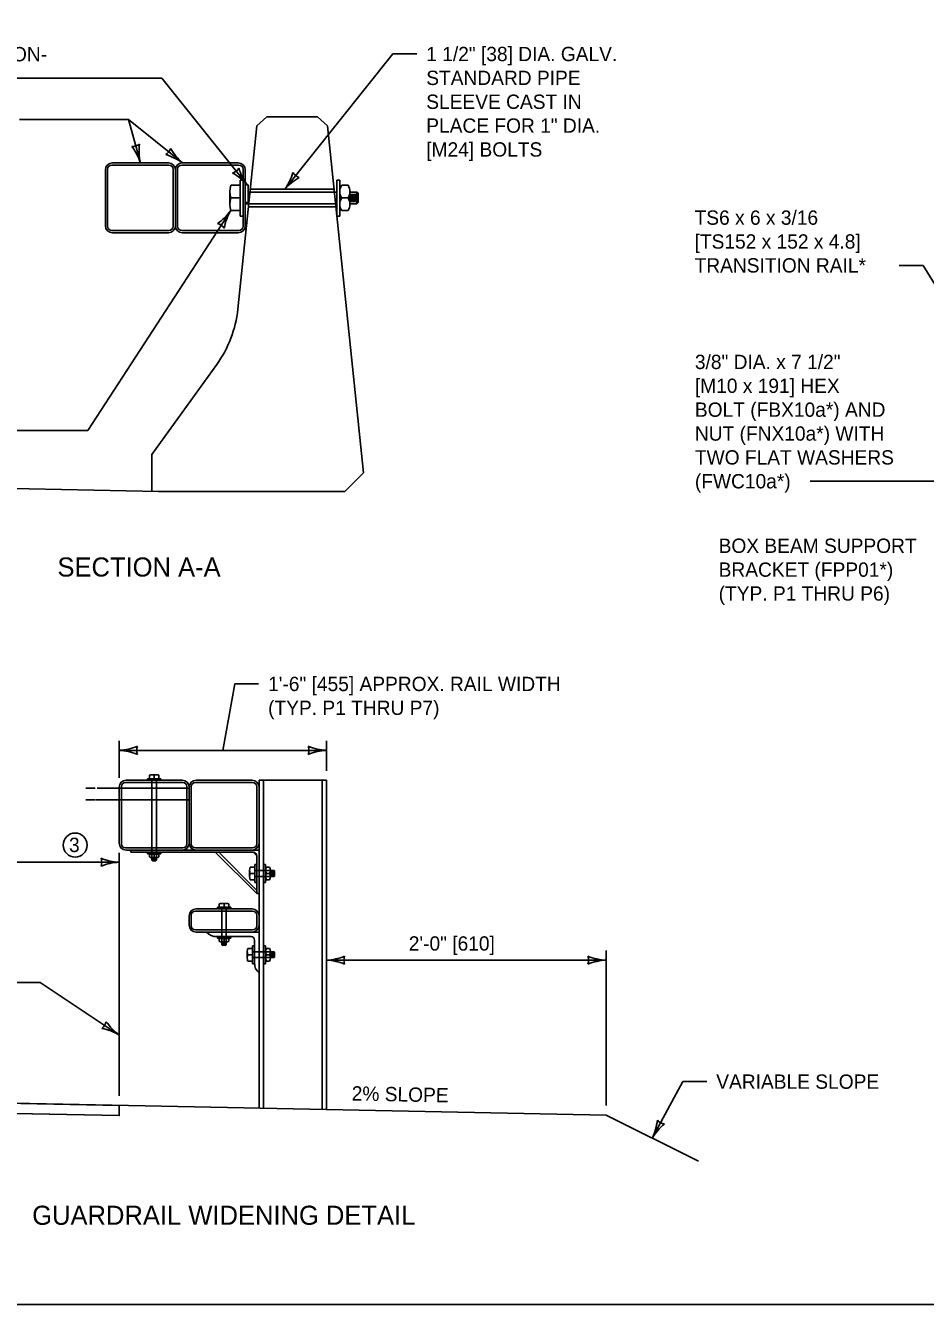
# Model space of a CAD drawing. Extents: x 49983 to 50021, y 49963.5 to 50011.4.
# Drawn here: x 50001.51 to 50005.28, y 49987.8 to 49993.16 of the extents above; entities that cross this region are included whole.
import ezdxf

# ---------------------------------------------------------------- set-up
doc = ezdxf.new("R2010")
doc.units = 0
for name, color, linetype in [('Level 1', 7, 'Continuous'), ('Level 10', 7, 'Continuous'), ('Level 2', 7, 'Continuous'), ('Level 3', 7, 'Continuous'), ('Level 4', 7, 'Continuous')]:
    doc.layers.add(name, color=color, linetype=linetype)

msp = doc.modelspace()

# ---------------------------------------------------------------- linework, layer by layer
at = {"layer": 'Level 1'}
for p, q in [((50002.5172, 49992.7754), (50002.4748, 49992.7371)), ((50002.7291, 49992.7754), (50002.5172, 49992.7754)), ((50002.7208, 49992.7754), (50002.5255, 49992.7754)), ((50002.7714, 49992.7371), (50002.7291, 49992.7754)), ((50002.4748, 49992.7371), (50002.3955, 49991.9692)), ((50002.9217, 49991.2832), (50002.7714, 49992.7371)), ((50001.8413, 49992.5533), (50001.8413, 49992.3191)), ((50001.8504, 49992.5559), (50001.8504, 49992.3165)), ((50001.868, 49992.5735), (50002.1074, 49992.5735)), ((50001.8706, 49992.5826), (50002.1048, 49992.5826)), ((50002.125, 49992.5559), (50002.125, 49992.3165)), ((50002.1341, 49992.5533), (50002.1341, 49992.3191)), ((50002.1341, 49992.5533), (50002.1341, 49992.3191)), ((50002.1433, 49992.5559), (50002.1433, 49992.3165)), ((50002.1609, 49992.5735), (50002.4002, 49992.5735)), ((50002.1634, 49992.5826), (50002.3976, 49992.5826)), ((50002.4178, 49992.5559), (50002.4178, 49992.3165)), ((50002.4269, 49992.5533), (50002.4269, 49992.3191)), ((50002.366, 49992.4885), (50002.4057, 49992.4885)), ((50002.4057, 49992.3598), (50002.4057, 49992.5101)), ((50002.4057, 49992.5101), (50002.4178, 49992.5101)), ((50002.4389, 49992.4905), (50002.4269, 49992.4905)), ((50002.4389, 49992.417), (50002.4389, 49992.4905)), ((50002.8225, 49992.5101), (50002.8104, 49992.5101)), ((50002.8104, 49992.3598), (50002.8104, 49992.5101)), ((50002.8225, 49992.3598), (50002.8225, 49992.5101)), ((50002.8573, 49992.4885), (50002.8307, 49992.4885)), ((50002.3628, 49992.409), (50002.3628, 49992.462)), ((50002.366, 49992.4355), (50002.4057, 49992.4355)), ((50002.4389, 49992.46), (50002.4462, 49992.46)), ((50002.8104, 49992.46), (50002.8001, 49992.46)), ((50002.8307, 49992.4355), (50002.8573, 49992.4355)), ((50002.8655, 49992.409), (50002.8655, 49992.462)), ((50002.8946, 49992.46), (50002.8655, 49992.46)), ((50002.8723, 49992.4181), (50002.8723, 49992.4526)), ((50002.8772, 49992.4181), (50002.8772, 49992.4526)), ((50002.8822, 49992.4181), (50002.8822, 49992.4526)), ((50002.8871, 49992.4181), (50002.8871, 49992.4526)), ((50002.8946, 49992.46), (50002.8995, 49992.4551)), ((50002.8946, 49992.46), (50002.8946, 49992.4109)), ((50002.8946, 49992.46), (50002.8995, 49992.4551)), ((50002.8995, 49992.4158), (50002.8995, 49992.4551)), ((50002.8995, 49992.4158), (50002.8995, 49992.4551)), ((50002.366, 49992.3825), (50002.4057, 49992.3825)), ((50002.4389, 49992.417), (50002.4269, 49992.417)), ((50002.4269, 49992.4109), (50002.4411, 49992.4109)), ((50002.8104, 49992.4109), (50002.8051, 49992.4109)), ((50002.8573, 49992.3825), (50002.8307, 49992.3825)), ((50002.8946, 49992.4109), (50002.8655, 49992.4109)), ((50002.8946, 49992.4109), (50002.8655, 49992.4109)), ((50002.8946, 49992.4109), (50002.8995, 49992.4158)), ((50002.8946, 49992.4109), (50002.8995, 49992.4158)), ((50002.4057, 49992.3598), (50002.4178, 49992.3598)), ((50002.8225, 49992.3598), (50002.8104, 49992.3598)), ((50001.868, 49992.2989), (50002.1074, 49992.2989)), ((50001.8706, 49992.2898), (50002.1048, 49992.2898)), ((50002.1609, 49992.2989), (50002.4002, 49992.2989)), ((50002.1634, 49992.2898), (50002.3976, 49992.2898)), ((50002.3072, 49991.7374), (50002.0357, 49991.3602)), ((50002.0357, 49991.3602), (50002.0357, 49991.2061)), ((50002.8446, 49991.2061), (50002.9217, 49991.2832)), ((50001.2282, 49991.2223), (50002.0637, 49991.2056)), ((50002.0637, 49991.2056), (50002.8446, 49991.2056)), ((50001.9257, 49989.9862), (50002.165, 49989.9862)), ((50001.9283, 49989.9953), (50002.1625, 49989.9953)), ((50002.0172, 49990.0019), (50002.0732, 49990.0019)), ((50002.0172, 49990.0019), (50002.0172, 49989.9953)), ((50002.0256, 49990.0167), (50002.0256, 49990.0019)), ((50002.0355, 49990.0179), (50002.0552, 49990.0179)), ((50002.0362, 49989.7117), (50002.0362, 49989.9862)), ((50002.0454, 49990.0167), (50002.0454, 49990.0019)), ((50002.0545, 49989.7117), (50002.0545, 49989.9862)), ((50002.0651, 49990.0167), (50002.0651, 49990.0019)), ((50002.0732, 49990.0019), (50002.0732, 49989.9953)), ((50002.2185, 49989.9862), (50002.4579, 49989.9862)), ((50002.2211, 49989.9953), (50002.4553, 49989.9953)), ((50002.4846, 49989.9953), (50002.4846, 49989.7025)), ((50002.4846, 49989.8032), (50002.4846, 49989.9953)), ((50002.7668, 49989.9953), (50002.4846, 49989.9953)), ((50002.4846, 49988.6212), (50002.4846, 49989.9953)), ((50002.5026, 49988.6208), (50002.5026, 49989.9953)), ((50002.7488, 49989.9171), (50002.7488, 49989.9953)), ((50002.7488, 49988.6159), (50002.7488, 49989.9953)), ((50002.7668, 49988.6155), (50002.7668, 49989.9953)), ((50001.899, 49989.966), (50001.899, 49989.7318)), ((50001.9081, 49989.9686), (50001.9081, 49989.7293)), ((50002.1826, 49989.9686), (50002.1826, 49989.7293)), ((50002.1918, 49989.966), (50002.1918, 49989.7318)), ((50002.1918, 49989.966), (50002.1918, 49989.7318)), ((50002.2009, 49989.9686), (50002.2009, 49989.7293)), ((50002.4755, 49989.9686), (50002.4755, 49989.7293)), ((50002.4846, 49989.8993), (50002.4846, 49989.8993)), ((50002.7488, 49989.8032), (50002.7488, 49989.8815)), ((50001.9257, 49989.7117), (50002.165, 49989.7117)), ((50001.9283, 49989.7025), (50002.1918, 49989.7025)), ((50001.9477, 49989.7025), (50002.4846, 49989.7025)), ((50001.9477, 49989.6934), (50001.9477, 49989.7025)), ((50002.1918, 49989.7025), (50002.4846, 49989.7025)), ((50002.2185, 49989.7117), (50002.4579, 49989.7117)), ((50002.4846, 49989.7025), (50002.4846, 49989.5207)), ((50001.9477, 49989.6934), (50002.4608, 49989.6934)), ((50002.0175, 49989.6868), (50002.0175, 49989.6934)), ((50002.0736, 49989.6868), (50002.0175, 49989.6868)), ((50002.0256, 49989.6739), (50002.0256, 49989.6837)), ((50002.0552, 49989.6708), (50002.0355, 49989.6708)), ((50002.0362, 49989.66), (50002.0362, 49989.6708)), ((50002.0545, 49989.66), (50002.0362, 49989.66)), ((50002.0362, 49989.66), (50002.038, 49989.6581)), ((50002.038, 49989.6581), (50002.0527, 49989.6581)), ((50002.0389, 49989.6683), (50002.0517, 49989.6683)), ((50002.0389, 49989.6664), (50002.0517, 49989.6664)), ((50002.0389, 49989.6646), (50002.0517, 49989.6646)), ((50002.0389, 49989.6627), (50002.0517, 49989.6627)), ((50002.0454, 49989.6837), (50002.0454, 49989.6739)), ((50002.0545, 49989.66), (50002.0527, 49989.6581)), ((50002.0545, 49989.66), (50002.0545, 49989.6708)), ((50002.0651, 49989.6739), (50002.0651, 49989.6837)), ((50002.0736, 49989.6868), (50002.0736, 49989.6934)), ((50002.4755, 49989.5207), (50002.3029, 49989.6933)), ((50002.3157, 49989.6934), (50002.4755, 49989.5337)), ((50002.4608, 49989.6934), (50002.4755, 49989.6787)), ((50002.4755, 49989.6787), (50002.4755, 49989.5207)), ((50002.4452, 49989.5917), (50002.4452, 49989.6182)), ((50002.4468, 49989.6314), (50002.4666, 49989.6314)), ((50002.4468, 49989.6049), (50002.4666, 49989.6049)), ((50002.4666, 49989.5671), (50002.4666, 49989.6422)), ((50002.4666, 49989.6422), (50002.4755, 49989.6422)), ((50002.5115, 49989.6422), (50002.5026, 49989.6422)), ((50002.5115, 49989.5671), (50002.5115, 49989.6422)), ((50002.5288, 49989.6314), (50002.5156, 49989.6314)), ((50002.5156, 49989.6049), (50002.5288, 49989.6049)), ((50002.5329, 49989.5917), (50002.5329, 49989.6182)), ((50002.5475, 49989.6172), (50002.5329, 49989.6172)), ((50002.5363, 49989.5962), (50002.5363, 49989.6135)), ((50002.5388, 49989.5962), (50002.5388, 49989.6135)), ((50002.5413, 49989.5962), (50002.5413, 49989.6135)), ((50002.5437, 49989.5962), (50002.5437, 49989.6135)), ((50002.5475, 49989.6172), (50002.5475, 49989.5926)), ((50002.5475, 49989.6172), (50002.5499, 49989.6147)), ((50002.5475, 49989.5926), (50002.5499, 49989.5951)), ((50002.5499, 49989.5951), (50002.5499, 49989.6147)), ((50002.4468, 49989.5784), (50002.4666, 49989.5784)), ((50002.4666, 49989.5671), (50002.4755, 49989.5671)), ((50002.5115, 49989.5671), (50002.5026, 49989.5671)), ((50002.5288, 49989.5784), (50002.5156, 49989.5784)), ((50002.5475, 49989.5926), (50002.5329, 49989.5926)), ((50002.4846, 49989.5207), (50002.4755, 49989.5207)), ((50002.4579, 49989.4474), (50002.2185, 49989.4474)), ((50002.4553, 49989.4566), (50002.2211, 49989.4566)), ((50002.3661, 49989.4632), (50002.3101, 49989.4632)), ((50002.3101, 49989.4632), (50002.3101, 49989.4566)), ((50002.3182, 49989.478), (50002.3182, 49989.4632)), ((50002.3478, 49989.4792), (50002.328, 49989.4792)), ((50002.3288, 49989.3681), (50002.3288, 49989.4474)), ((50002.3379, 49989.478), (50002.3379, 49989.4632)), ((50002.3471, 49989.3681), (50002.3471, 49989.4474)), ((50002.3577, 49989.478), (50002.3577, 49989.4632)), ((50002.3661, 49989.4632), (50002.3661, 49989.4566)), ((50002.1918, 49989.4273), (50002.1918, 49989.3883)), ((50002.2009, 49989.4298), (50002.2009, 49989.3857)), ((50002.4755, 49989.4298), (50002.4755, 49989.3857)), ((50002.4579, 49989.3681), (50002.2185, 49989.3681)), ((50002.4846, 49989.359), (50002.2211, 49989.359)), ((50002.265, 49989.359), (50002.4846, 49989.359)), ((50002.3068, 49989.34), (50002.451, 49989.34)), ((50002.3101, 49989.3334), (50002.3101, 49989.34)), ((50002.3661, 49989.3334), (50002.3101, 49989.3334)), ((50002.3182, 49989.3205), (50002.3182, 49989.3304)), ((50002.3379, 49989.3304), (50002.3379, 49989.3205)), ((50002.3577, 49989.3205), (50002.3577, 49989.3304)), ((50002.3661, 49989.3334), (50002.3661, 49989.34)), ((50002.3478, 49989.3174), (50002.328, 49989.3174)), ((50002.3288, 49989.3066), (50002.3288, 49989.3174)), ((50002.347, 49989.3066), (50002.3288, 49989.3066)), ((50002.3288, 49989.3066), (50002.3306, 49989.3048)), ((50002.3306, 49989.3048), (50002.3452, 49989.3048)), ((50002.3314, 49989.3149), (50002.3443, 49989.3149)), ((50002.3314, 49989.313), (50002.3443, 49989.313)), ((50002.3314, 49989.3112), (50002.3443, 49989.3112)), ((50002.3314, 49989.3094), (50002.3443, 49989.3094)), ((50002.347, 49989.3066), (50002.3452, 49989.3048)), ((50002.347, 49989.3066), (50002.347, 49989.3174)), ((50002.4354, 49989.251), (50002.4354, 49989.2775)), ((50002.437, 49989.2908), (50002.4568, 49989.2908)), ((50002.4568, 49989.2264), (50002.4568, 49989.3016)), ((50002.4568, 49989.3016), (50002.4657, 49989.3016)), ((50002.4657, 49989.23), (50002.4657, 49989.3254)), ((50002.5115, 49989.3016), (50002.5026, 49989.3016)), ((50002.5115, 49989.2264), (50002.5115, 49989.3016)), ((50002.5288, 49989.2908), (50002.5156, 49989.2908)), ((50002.5329, 49989.251), (50002.5329, 49989.2775)), ((50002.5475, 49989.2765), (50002.5329, 49989.2765)), ((50002.5363, 49989.2555), (50002.5363, 49989.2728)), ((50002.5388, 49989.2555), (50002.5388, 49989.2728)), ((50002.5413, 49989.2555), (50002.5413, 49989.2728)), ((50002.5437, 49989.2555), (50002.5437, 49989.2728)), ((50002.5475, 49989.2765), (50002.5475, 49989.252)), ((50002.5475, 49989.2765), (50002.5499, 49989.2741)), ((50002.5499, 49989.2544), (50002.5499, 49989.2741)), ((50002.437, 49989.2643), (50002.4568, 49989.2643)), ((50002.437, 49989.2377), (50002.4568, 49989.2377)), ((50002.4568, 49989.2264), (50002.4657, 49989.2264)), ((50002.5115, 49989.2264), (50002.5026, 49989.2264)), ((50002.5156, 49989.2643), (50002.5288, 49989.2643)), ((50002.5288, 49989.2377), (50002.5156, 49989.2377)), ((50002.5475, 49989.252), (50002.5329, 49989.252)), ((50002.5475, 49989.252), (50002.5499, 49989.2544)), ((50000.6639, 49988.6576), (50003.938, 49988.5921)), ((50001.899, 49988.6329), (50001.899, 49988.5902)), ((50000.6639, 49988.6149), (50001.899, 49988.5902)), ((50003.938, 49988.5921), (50004.3249, 49988.3987))]:
    msp.add_line(p, q, dxfattribs=at)
msp.add_lwpolyline([(49999.3835, 49998.9992), (50016.7501, 49998.9992), (50016.7501, 49987.7988), (49999.3835, 49987.7988)], close=True, dxfattribs=at)
msp.add_lwpolyline([(50001.899, 49988.6329), (50000.6639, 49988.6576), (50000.6639, 49988.6149), (50001.899, 49988.5902), (50001.899, 49988.6329)], dxfattribs=at)
for centre, radius, start, end in [((50001.8706, 49992.5533), 0.0293, 90, 180), ((50001.868, 49992.5559), 0.0176, 90, 180), ((50002.1048, 49992.5533), 0.0293, 0, 90), ((50002.1074, 49992.5559), 0.0176, 0, 90), ((50002.1634, 49992.5533), 0.0293, 90, 180), ((50002.1609, 49992.5559), 0.0176, 90, 180), ((50002.3976, 49992.5533), 0.0293, 0, 90), ((50002.4002, 49992.5559), 0.0176, 0, 90), ((50002.4741, 49992.462), 0.1113, 166.2307, 193.7693), ((50002.8695, 49992.462), 0.0469, 145.616, 214.384), ((50002.8185, 49992.462), 0.0469, 325.616, 34.384), ((50002.4741, 49992.409), 0.1113, 166.2307, 193.7693), ((50002.8695, 49992.409), 0.0469, 145.616, 214.384), ((50002.8185, 49992.409), 0.0469, 325.616, 34.384), ((50001.8706, 49992.3191), 0.0293, 180, 270), ((50001.868, 49992.3165), 0.0176, 180, 270), ((50002.1048, 49992.3191), 0.0293, 270, 0), ((50002.1074, 49992.3165), 0.0176, 270, 0), ((50002.1634, 49992.3191), 0.0293, 180, 270), ((50002.1609, 49992.3165), 0.0176, 180, 270), ((50002.3976, 49992.3191), 0.0293, 270, 0), ((50002.4002, 49992.3165), 0.0176, 270, 0), ((50001.9283, 49989.966), 0.0293, 90, 180), ((50001.9257, 49989.9686), 0.0176, 90, 180), ((50002.0355, 49989.9764), 0.0415, 76.2307, 103.7693), ((50002.0552, 49989.9764), 0.0415, 76.2307, 103.7693), ((50002.1625, 49989.966), 0.0293, 0, 90), ((50002.165, 49989.9686), 0.0176, 0, 90), ((50002.2211, 49989.966), 0.0293, 90, 180), ((50002.2185, 49989.9686), 0.0176, 90, 180), ((50002.4553, 49989.966), 0.0293, 0, 90), ((50002.4579, 49989.9686), 0.0176, 0, 90), ((50001.9283, 49989.7318), 0.0293, 180, 270), ((50001.9257, 49989.7293), 0.0176, 180, 270), ((50002.1625, 49989.7318), 0.0293, 270, 0), ((50002.165, 49989.7293), 0.0176, 270, 0), ((50002.2211, 49989.7318), 0.0293, 180, 270), ((50002.2185, 49989.7293), 0.0176, 180, 270), ((50002.4553, 49989.7318), 0.0293, 270, 0), ((50002.4579, 49989.7293), 0.0176, 270, 0), ((50002.0355, 49989.6693), 0.0175, 55.616, 124.384), ((50002.0355, 49989.6883), 0.0175, 235.616, 304.384), ((50002.0552, 49989.6693), 0.0175, 55.616, 124.384), ((50002.0552, 49989.6883), 0.0175, 235.616, 304.384), ((50002.4608, 49989.6787), 0.0146, 0, 90), ((50002.5009, 49989.6182), 0.0557, 166.2307, 193.7693), ((50002.5009, 49989.5917), 0.0557, 166.2307, 193.7693), ((50002.5349, 49989.6182), 0.0235, 145.616, 214.384), ((50002.5349, 49989.5917), 0.0235, 145.616, 214.384), ((50002.5094, 49989.6182), 0.0235, 325.616, 34.384), ((50002.5094, 49989.5917), 0.0235, 325.616, 34.384), ((50002.2211, 49989.4273), 0.0293, 90, 180), ((50002.2185, 49989.4298), 0.0176, 90, 180), ((50002.328, 49989.4377), 0.0415, 76.2307, 103.7693), ((50002.3478, 49989.4377), 0.0415, 76.2307, 103.7693), ((50002.4553, 49989.4273), 0.0293, 0, 90), ((50002.4579, 49989.4298), 0.0176, 0, 90), ((50002.2211, 49989.3883), 0.0293, 180, 270), ((50002.2185, 49989.3857), 0.0176, 180, 270), ((50002.4553, 49989.3883), 0.0293, 270, 0), ((50002.4579, 49989.3857), 0.0176, 270, 0), ((50002.3051, 49989.3918), 0.0518, 219.3297, 271.9596), ((50002.328, 49989.3159), 0.0175, 55.616, 124.384), ((50002.3478, 49989.3159), 0.0175, 55.616, 124.384), ((50002.451, 49989.3254), 0.0146, 0, 90), ((50002.328, 49989.3349), 0.0175, 235.616, 304.384), ((50002.3478, 49989.3349), 0.0175, 235.616, 304.384), ((50002.491, 49989.2775), 0.0557, 166.2307, 193.7693), ((50002.5349, 49989.2775), 0.0235, 145.616, 214.384), ((50002.5094, 49989.2775), 0.0235, 325.616, 34.384), ((50002.491, 49989.251), 0.0557, 166.2307, 193.7693), ((50002.5174, 49989.2282), 0.0518, 178.0404, 230.6703), ((50002.5349, 49989.251), 0.0235, 145.616, 214.384), ((50002.5094, 49989.251), 0.0235, 325.616, 34.384)]:
    msp.add_arc(centre, radius, start, end, dxfattribs=at)
msp.add_ellipse((50001.9166, 49992.0186), major_axis=(0.4815, 0), ratio=0.999642, start_param=5.659162, end_param=6.180346, dxfattribs=at)
at = {"layer": 'Level 10'}
for p, q in [((50002.0362, 49989.9862), (50002.0362, 49990.0019)), ((50002.0545, 49989.9862), (50002.0545, 49990.0019)), ((50001.7597, 49989.9619), (50001.7985, 49989.9619)), ((50001.8067, 49989.9619), (50002.1897, 49989.9619)), ((50001.7597, 49989.9127), (50001.7985, 49989.9127)), ((50001.8012, 49989.9127), (50002.1897, 49989.9127)), ((50002.0362, 49989.7117), (50002.0362, 49989.6708)), ((50002.0545, 49989.7117), (50002.0545, 49989.6708)), ((50002.4666, 49989.6172), (50002.5329, 49989.6172)), ((50002.4666, 49989.5926), (50002.5329, 49989.5926)), ((50002.3288, 49989.4474), (50002.3288, 49989.4632)), ((50002.3471, 49989.4474), (50002.3471, 49989.4632)), ((50002.3288, 49989.3681), (50002.3288, 49989.3174)), ((50002.3471, 49989.3681), (50002.3471, 49989.3174)), ((50002.4568, 49989.2765), (50002.5329, 49989.2765)), ((50002.4568, 49989.252), (50002.5329, 49989.252))]:
    msp.add_line(p, q, dxfattribs=at)
at = {"layer": 'Level 2'}
msp.add_circle((50001.7145, 49989.7238), 0.0503, dxfattribs=at)
at = {"layer": 'Level 3'}
for p, q in [((50002.5922, 49992.4718), (50003.0449, 49993.0388)), ((50003.0449, 49993.0388), (50003.1449, 49993.0388)), ((50001.3817, 49992.9381), (50002.0776, 49992.9381)), ((50002.4347, 49992.4905), (50002.0776, 49992.9381)), ((50001.9382, 49992.7642), (50002.1634, 49992.5826)), ((50002.366, 49992.3825), (50001.7673, 49991.4614)), ((50005.266, 49992.1531), (50005.166, 49992.1531)), ((50005.4693, 49991.8223), (50005.266, 49992.1531)), ((50001.7673, 49991.4614), (50001.2468, 49991.4614)), ((50001.899, 49990.006), (50001.899, 49990.1607)), ((50002.7668, 49990.0353), (50002.7668, 49990.1607)), ((50001.899, 49990.1207), (50002.7668, 49990.1207)), ((50000.7278, 49989.6518), (50001.899, 49989.6518)), ((50001.899, 49989.6918), (50001.899, 49988.6729)), ((50003.938, 49988.6321), (50003.938, 49989.2814)), ((50002.7668, 49989.2414), (50003.938, 49989.2414))]:
    msp.add_line(p, q, dxfattribs=at)
for points in [[(50001.4808, 49992.7642), (50001.9382, 49992.7642), (50001.9877, 49992.5826)], [(50004.7931, 49991.2484), (50005.4283, 49991.2484), (50005.8926, 49991.4839)], [(50002.4826, 49990.399), (50002.3826, 49990.399), (50002.3329, 49990.1207)], [(50001.4675, 49989.1482), (50001.5675, 49989.1482), (50001.899, 49988.9276)], [(50004.1314, 49988.4954), (50004.2596, 49988.7324), (50004.3596, 49988.7324)]]:
    msp.add_lwpolyline(points, dxfattribs=at)
for centre, radius, start, end in [((50001.954, 49992.7063), 0.0548, 267.3865, 303.1088), ((50001.7662, 49992.5103), 0.233, 18.075, 37.3248), ((50002.2044, 49992.6322), 0.2223, 172.7037, 192.8872), ((50002.0636, 49992.6631), 0.0548, 303.2641, 338.9865), ((50002.0263, 49992.3942), 0.233, 53.9526, 73.2024), ((50002.31, 49992.7498), 0.2223, 208.5813, 228.7648), ((50002.3547, 49992.5908), 0.0548, 290.7201, 326.4425), ((50002.614, 49992.6219), 0.2223, 196.0373, 216.2208), ((50002.4032, 49992.608), 0.233, 324.2261, 343.476), ((50002.6722, 49992.572), 0.0548, 213.5376, 249.26), ((50002.2599, 49992.3364), 0.233, 41.4086, 60.6585), ((50002.7601, 49992.3261), 0.2223, 118.8548, 139.0383), ((50002.1847, 49992.5112), 0.2223, 304.4354, 324.6189), ((50002.5674, 49992.2653), 0.233, 149.8067, 169.0565), ((50002.2961, 49992.275), 0.0548, 39.1182, 74.8406), ((50001.8875, 49990.3535), 0.233, 272.8273, 292.0772), ((50002.0272, 49990.1207), 0.0548, 162.1388, 197.8612), ((50002.6386, 49990.1207), 0.0548, 342.1388, 17.8612), ((50002.7783, 49990.3535), 0.233, 247.9228, 267.1727), ((50001.8898, 49989.8986), 0.2223, 67.456, 87.6395), ((50002.776, 49989.8986), 0.2223, 92.3605, 112.544), ((50001.7707, 49989.6518), 0.0548, 342.1388, 17.8612), ((50001.9105, 49989.8845), 0.233, 247.9228, 267.1727), ((50001.9081, 49989.4297), 0.2223, 92.3605, 112.544), ((50002.7553, 49989.4741), 0.233, 272.8273, 292.0772), ((50002.7577, 49989.0193), 0.2223, 67.456, 87.6395), ((50002.895, 49989.2414), 0.0548, 162.1388, 197.8612), ((50003.8098, 49989.2414), 0.0548, 342.1388, 17.8612), ((50003.9495, 49989.4741), 0.233, 247.9228, 267.1727), ((50003.9472, 49989.0193), 0.2223, 92.3605, 112.544), ((50001.7922, 49988.9986), 0.0548, 308.4906, 344.213), ((50001.7796, 49988.7275), 0.233, 59.1791, 78.429), ((50002.0297, 49989.1074), 0.2223, 213.8078, 233.9913), ((50003.9213, 49988.596), 0.233, 334.4243, 353.6742), ((50004.3225, 49988.3817), 0.2223, 129.053, 149.2366), ((50004.1924, 49988.6082), 0.0548, 223.7359, 259.4582)]:
    msp.add_arc(centre, radius, start, end, dxfattribs=at)
at = {"layer": 'Level 4'}
for p, q in [((50002.4462, 49992.46), (50002.8001, 49992.46)), ((50002.7988, 49992.4718), (50002.4474, 49992.4718)), ((50002.8065, 49992.3981), (50002.4398, 49992.3981)), ((50002.4411, 49992.4109), (50002.8051, 49992.4109))]:
    msp.add_line(p, q, dxfattribs=at)

# ---------------------------------------------------------------- texts
at = {"layer": 'Level 1'}
msp.add_text('3', height=0.06, dxfattribs=at).set_placement((50001.6887, 49989.6945))
at = {"layer": 'Level 2'}
for s, height, p in [('1/4" [6.4] SHIM PLATE* (FOR NON-', 0.06, (50000.3022, 49993.0081)), ('1 1/2" [38] DIA. GALV.', 0.06, (50003.1849, 49993.0088)), ('STANDARD PIPE', 0.06, (50003.1849, 49992.9088)), ('SLEEVE CAST IN', 0.06, (50003.1849, 49992.8088)), ('PLACE FOR 1" DIA. ', 0.06, (50003.1849, 49992.7088)), ('[M24] BOLTS', 0.06, (50003.1849, 49992.6088)), ('3/8" DIA. x 7 1/2" ', 0.06, (50004.3101, 49991.7184)), ('[M10 x 191] HEX', 0.06, (50004.3101, 49991.6184)), ('BOLT (FBX10a*) AND', 0.06, (50004.3101, 49991.5184)), ('NUT (FNX10a*) WITH', 0.06, (50004.3101, 49991.4184)), ('TWO FLAT WASHERS', 0.06, (50004.3101, 49991.3184)), ('(FWC10a*)', 0.06, (50004.3101, 49991.2184)), ('BOX BEAM SUPPORT', 0.06, (50004.4096, 49990.9481)), ('SECTION A-A', 0.08, (50001.6402, 49990.849)), ('BRACKET (FPP01*)', 0.06, (50004.4096, 49990.8481)), ('(TYP. P1 THRU P6)', 0.06, (50004.4096, 49990.7481)), ('1\'-6" [455] APPROX. RAIL WIDTH', 0.06, (50002.5226, 49990.369)), ('(TYP. P1 THRU P7)', 0.06, (50002.5226, 49990.269)), ('2\'-0" [610]', 0.06, (50003.1118, 49989.2814)), ('VARIABLE SLOPE', 0.06, (50004.3996, 49988.7024)), ('GUARDRAIL WIDENING DETAIL', 0.08, (50001.5345, 49988.1325))]:
    msp.add_text(s, height=height, dxfattribs=at).set_placement(p)
for s, rotation, p in [('TS6 x 6 x 3/16', 360, (50004.3088, 49992.3231)), ('[TS152 x 152 x 4.8]', 360, (50004.3088, 49992.2231)), ('TRANSITION RAIL*', 360, (50004.3088, 49992.1231)), ('2% SLOPE', 358.8542, (50002.8722, 49988.6534))]:
    msp.add_text(s, height=0.06, rotation=rotation, dxfattribs=at).set_placement(p)

doc.saveas('drawing.dxf')
